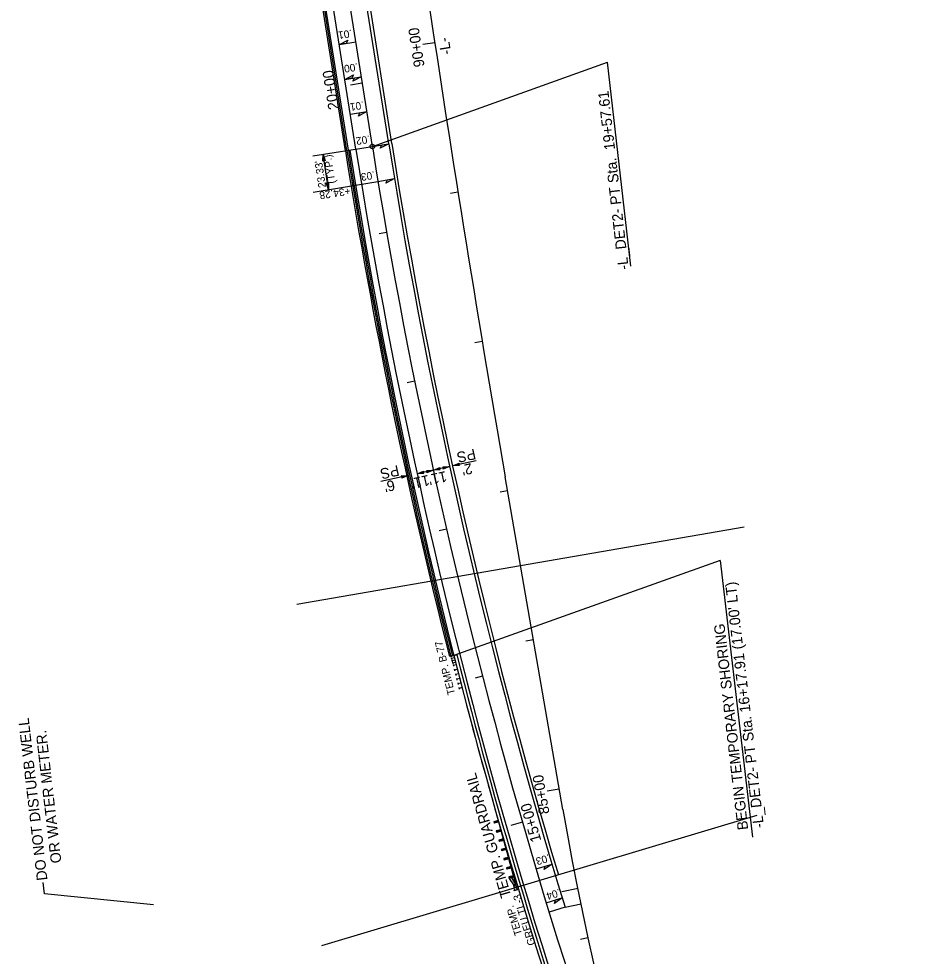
# Model space of a CAD drawing. Extents: x 473658 to 481584, y 489119 to 506230.
# Drawn here: x 478076 to 478674, y 495025 to 495645 of the extents above; entities that cross this region are included whole.
import ezdxf

# ---------------------------------------------------------------- set-up
doc = ezdxf.new("R2010")
doc.units = 0
for name, color, linetype in [('Exist Structure Minor Culvert Topo', 7, 'Continuous'), ('Exist Structure Minor Pipes CMP 60 Inch', 7, 'Continuous'), ('Prop Conc Barrier', 7, 'Continuous'), ('Prop Dimension', 7, 'Continuous'), ('Prop EOT', 7, 'Continuous'), ('Prop Guardrail', 7, 'Continuous'), ('Prop Guardrail Anchor Unit CELL', 7, 'Continuous'), ('Prop Horizontal Alignment', 7, 'Continuous'), ('Prop Horizontal Alignment Direction Label', 7, 'Continuous'), ('Prop Horizontal Alignment Station Label', 7, 'Continuous'), ('Prop Horizontal Alignment Tick Label', 7, 'Continuous'), ('Prop Horizontal Alignment Tick Large', 7, 'Continuous'), ('Prop Horizontal Alignment Tick Small', 7, 'Continuous'), ('Prop Paved Shoulder', 7, 'Continuous'), ('Prop Superelevation  Arrow CELL', 7, 'Continuous'), ('Prop Superelevation Label', 7, 'Continuous'), ('Scratch_Level_3', 7, 'Continuous'), ('Scratch_Level_4', 7, 'Continuous'), ('Scratch_Level_5', 7, 'Continuous'), ('Scratch_Level_6', 7, 'Continuous'), ('Sheet Plan And Profile CELL', 7, 'Continuous'), ('Sheet Profile Grid Major CELL', 7, 'Continuous')]:
    doc.layers.add(name, color=color, linetype=linetype)

msp = doc.modelspace()

# ---------------------------------------------------------------- linework, layer by layer
at = {"layer": 'Exist Structure Minor Culvert Topo'}
for p, q in [((478360.78, 495224.13), (478361.07, 495223.02)), ((478362.86, 495224.07), (478360.93, 495223.57)), ((478361.17, 495222.61), (478361.46, 495221.5)), ((478363.25, 495222.55), (478361.32, 495222.06)), ((478362.86, 495224.07), (478368.55, 495201.91)), ((478361.56, 495221.1), (478361.85, 495219.99)), ((478363.64, 495221.04), (478361.7, 495220.54)), ((478361.95, 495219.58), (478362.24, 495218.48)), ((478364.03, 495219.53), (478362.09, 495219.03)), ((478362.34, 495218.07), (478362.62, 495216.96)), ((478364.42, 495218.01), (478362.48, 495217.52)), ((478363.12, 495215.04), (478363.4, 495213.94)), ((478365.2, 495214.99), (478363.26, 495214.49)), ((478363.89, 495212.02), (478364.18, 495210.91)), ((478365.97, 495211.96), (478364.04, 495211.46)), ((478364.67, 495208.99), (478364.96, 495207.88)), ((478366.75, 495208.93), (478364.81, 495208.44)), ((478365.45, 495205.96), (478365.73, 495204.85)), ((478367.53, 495205.91), (478365.59, 495205.41)), ((478366.22, 495202.94), (478366.51, 495201.83)), ((478368.3, 495202.88), (478366.37, 495202.38))]:
    msp.add_line(p, q, dxfattribs=at)
at = {"layer": 'Exist Structure Minor Pipes CMP 60 Inch'}
msp.add_line((478291.29, 495557.58), (478258.12, 495767.21), dxfattribs=at)
msp.add_arc((481983.35, 496141.85), 3738, 188.99254, 194.22469, dxfattribs=at)
at = {"layer": 'Prop Conc Barrier'}
for p, q in [((478293.31, 495557.93), (478260.02, 495768.31)), ((478306.27, 495497.95), (478306.27, 495497.95))]:
    msp.add_line(p, q, dxfattribs=at)
msp.add_arc((481983.35, 496141.85), 3736, 188.99254, 194.22472, dxfattribs=at)
at = {"layer": 'Prop Dimension'}
for p, q in [((478377.54, 495352.74), (478362.05, 495349.35)), ((478360.1, 495348.92), (478338.61, 495344.22)), ((478332.74, 495342.94), (478314.7, 495338.99)), ((478092.44, 495066.56), (478091.55, 495074.21)), ((478164.55, 495059.32), (478092.44, 495066.56))]:
    msp.add_line(p, q, dxfattribs=at)
for points in [[(478344.79, 495346.37), (478349.35, 495346.57), (478345.1, 495344.82), (478345.49, 495345.73)], [(478353.91, 495346.78), (478349.35, 495346.57), (478353.6, 495348.32), (478353.21, 495347.42)], [(478355.53, 495348.72), (478360.1, 495348.92), (478355.85, 495347.17), (478356.24, 495348.08)], [(478366.61, 495349.56), (478362.05, 495349.35), (478366.3, 495351.1), (478365.91, 495350.19)], [(478328.18, 495342.73), (478332.74, 495342.94), (478328.49, 495341.19), (478328.89, 495342.09)], [(478343.17, 495344.42), (478338.61, 495344.22), (478342.85, 495345.97), (478342.46, 495345.06)]]:
    msp.add_lwpolyline(points, close=True, dxfattribs=at)
at = {"layer": 'Prop EOT'}
for p, q in [((478319.94, 495562.11), (478181.82, 496434.86)), ((478298.21, 495558.67), (478195, 496210.83))]:
    msp.add_line(p, q, dxfattribs=at)
for radius, end in [(3731, 203.7418), (3709, 196.99547)]:
    msp.add_arc((481983.35, 496141.85), radius, 188.99254, end, dxfattribs=at)
at = {"layer": 'Prop Guardrail'}
msp.add_arc((481983.35, 496141.85), 3735, 194.5756, 195.91787, dxfattribs=at)
at = {"layer": 'Prop Guardrail Anchor Unit CELL'}
for p, q in [((478391.56, 495117.49), (478403.8, 495072.37)), ((478392.23, 495115.04), (478389.33, 495114.25)), ((478391.04, 495113.68), (478389.33, 495114.25)), ((478389.33, 495114.25), (478389.59, 495113.29)), ((478389.59, 495113.29), (478390.78, 495114.65)), ((478392.49, 495114.07), (478389.59, 495113.29)), ((478390.78, 495114.65), (478391.04, 495113.68)), ((478390.78, 495114.65), (478392.49, 495114.07)), ((478391.04, 495113.68), (478392.23, 495115.04)), ((478392.49, 495114.07), (478391.04, 495113.68)), ((478392.23, 495115.04), (478392.49, 495114.07)), ((478393.88, 495108.96), (478390.93, 495108.16)), ((478392.67, 495107.59), (478390.93, 495108.16)), ((478390.93, 495108.16), (478391.19, 495107.19)), ((478391.19, 495107.19), (478392.4, 495108.56)), ((478394.14, 495107.99), (478391.19, 495107.19)), ((478392.4, 495108.56), (478392.67, 495107.59)), ((478392.4, 495108.56), (478394.14, 495107.99)), ((478393.88, 495108.96), (478392.67, 495107.59)), ((478395.53, 495102.88), (478392.58, 495102.08)), ((478394.32, 495101.51), (478392.58, 495102.08)), ((478392.58, 495102.08), (478392.85, 495101.11)), ((478392.85, 495101.11), (478394.06, 495102.48)), ((478395.79, 495101.91), (478392.85, 495101.11)), ((478394.06, 495102.48), (478394.32, 495101.51)), ((478394.06, 495102.48), (478395.79, 495101.91)), ((478395.53, 495102.88), (478394.32, 495101.51)), ((478397.18, 495096.79), (478394.25, 495096)), ((478395.97, 495095.43), (478394.25, 495096)), ((478394.25, 495096), (478394.51, 495095.03)), ((478394.51, 495095.03), (478395.71, 495096.4)), ((478397.44, 495095.83), (478394.51, 495095.03)), ((478395.71, 495096.4), (478395.97, 495095.43)), ((478395.71, 495096.4), (478397.44, 495095.83)), ((478397.18, 495096.79), (478395.97, 495095.43)), ((478397.18, 495096.79), (478397.44, 495095.83)), ((478398.82, 495090.71), (478395.8, 495089.89)), ((478397.57, 495089.34), (478395.8, 495089.89)), ((478395.8, 495089.89), (478396.06, 495088.93)), ((478396.06, 495088.93), (478397.31, 495090.3)), ((478399.09, 495089.75), (478396.06, 495088.93)), ((478397.31, 495090.3), (478397.57, 495089.34)), ((478397.31, 495090.3), (478399.09, 495089.75)), ((478398.82, 495090.71), (478397.57, 495089.34)), ((478400.47, 495084.63), (478397.58, 495083.85)), ((478399.29, 495083.27), (478397.58, 495083.85)), ((478397.58, 495083.85), (478397.84, 495082.88)), ((478397.84, 495082.88), (478399.03, 495084.24)), ((478400.74, 495083.67), (478397.84, 495082.88)), ((478399.03, 495084.24), (478399.29, 495083.27)), ((478399.03, 495084.24), (478400.74, 495083.67)), ((478400.47, 495084.63), (478399.29, 495083.27)), ((478402.12, 495078.55), (478399.17, 495077.75)), ((478400.91, 495077.18), (478399.17, 495077.75)), ((478399.17, 495077.75), (478399.43, 495076.78)), ((478399.43, 495076.78), (478400.64, 495078.15)), ((478402.38, 495077.58), (478399.43, 495076.78)), ((478399.43, 495076.78), (478402.22, 495072.46)), ((478400.64, 495078.15), (478400.91, 495077.18)), ((478400.64, 495078.15), (478402.38, 495077.58)), ((478402.12, 495078.55), (478400.91, 495077.18)), ((478400.91, 495077.18), (478403.67, 495072.85)), ((478403.67, 495072.85), (478402.22, 495072.46)), ((478402.22, 495072.46), (478402.35, 495071.98)), ((478403.93, 495071.89), (478402.22, 495072.46)), ((478402.22, 495072.46), (478402.48, 495071.5)), ((478402.48, 495071.5), (478403.67, 495072.85)), ((478403.93, 495071.89), (478402.48, 495071.5)), ((478402.56, 495071.98), (478403.15, 495072.15)), ((478403.13, 495070.01), (478402.56, 495071.98)), ((478402.64, 495068.64), (478403.13, 495070.01)), ((478405.46, 495069.47), (478402.64, 495068.64)), ((478403.15, 495072.15), (478403.73, 495072.32)), ((478403.73, 495072.32), (478404.3, 495070.35)), ((478404.3, 495070.35), (478405.46, 495069.47))]:
    msp.add_line(p, q, dxfattribs=at)
at = {"layer": 'Prop Horizontal Alignment'}
for p, q in [((478309.07, 495560.39), (478170.96, 496433.14)), ((478434.84, 495122.35), (478396.81, 495342.17))]:
    msp.add_line(p, q, dxfattribs=at)
for centre, radius, start, end in [((491911.02, 497680.41), 13715, 187.021509, 189.816184), ((481983.35, 496141.85), 3720, 188.99254, 203.7418), ((480454.83, 495471.85), 2050, 189.81618, 250.32977)]:
    msp.add_arc(centre, radius, start, end, dxfattribs=at)
at = {"layer": 'Prop Horizontal Alignment Station Label'}
for p, q in [((478309.07, 495560.39), (478464.32, 495616.2)), ((478479.87, 495481.31), (478464.32, 495616.2)), ((478538.89, 495286.79), (478362.86, 495224.07)), ((478538.89, 495286.79), (478560.07, 495104.01))]:
    msp.add_line(p, q, dxfattribs=at)
msp.add_circle((478309.07, 495560.39), 1.5, dxfattribs=at)
msp.add_circle((478309.07, 495560.39), 1.5, dxfattribs=at)
at = {"layer": 'Prop Horizontal Alignment Tick Large'}
for p, q in [((478350.31, 495628.98), (478342.4, 495627.79)), ((478302.45, 495602.26), (478294.54, 495601.01)), ((478432.51, 495135.8), (478424.63, 495134.44)), ((478408.18, 495113.94), (478400.5, 495111.73))]:
    msp.add_line(p, q, dxfattribs=at)
at = {"layer": 'Prop Horizontal Alignment Tick Small'}
for p, q in [((478365.62, 495530.17), (478360.69, 495529.38)), ((478318.52, 495503.56), (478313.59, 495502.7)), ((478381.66, 495431.46), (478376.73, 495430.64)), ((478337, 495405.29), (478332.1, 495404.3)), ((478398.42, 495332.87), (478393.49, 495332.02)), ((478358.11, 495307.54), (478353.24, 495306.42)), ((478415.46, 495234.34), (478410.54, 495233.49)), ((478381.85, 495210.4), (478377.01, 495209.15)), ((478451.35, 495037.6), (478446.46, 495036.54))]:
    msp.add_line(p, q, dxfattribs=at)
at = {"layer": 'Prop Paved Shoulder'}
for p, q in [((478321.91, 495562.42), (478183.8, 496435.17)), ((478292.28, 495557.74), (478258.98, 495768.15)), ((478360.93, 495223.57), (478364.8, 495224.55))]:
    msp.add_line(p, q, dxfattribs=at)
for radius, start, end in [(3737, 188.99254, 194.22469), (3707, 188.99254, 196.65704), (3733, 194.22478, 203.7418)]:
    msp.add_arc((481983.35, 496141.85), radius, start, end, dxfattribs=at)
at = {"layer": 'Prop Superelevation  Arrow CELL'}
for points in [[(478287.27, 495627.8), (478292.88, 495630.71), (478291.84, 495628.52)], [(478290.91, 495604.76), (478296.53, 495607.67), (478295.48, 495605.48)], [(478301.78, 495606.48), (478296.16, 495603.56), (478297.21, 495605.75)], [(478305.42, 495583.43), (478299.81, 495580.52), (478300.86, 495582.71)], [(478319.94, 495562.11), (478314.32, 495559.2), (478315.37, 495561.39)], [(478276.4, 495550.67), (478276.49, 495555.23), (478277.96, 495550.88), (478277.08, 495551.33)], [(478323.64, 495539.15), (478318.05, 495536.2), (478319.08, 495538.39)], [(478280.13, 495536.53), (478280.05, 495531.97), (478278.57, 495536.32), (478279.45, 495535.87)], [(478427.74, 495086.23), (478422.56, 495082.6), (478423.31, 495084.91)], [(478434.43, 495063.95), (478429.27, 495060.29), (478430.01, 495062.61)]]:
    msp.add_lwpolyline(points, close=True, dxfattribs=at)
at = {"layer": 'Prop Superelevation Label'}
for p, q in [((478287.27, 495627.8), (478298.13, 495629.52)), ((478290.91, 495604.76), (478301.78, 495606.48)), ((478294.56, 495581.71), (478305.42, 495583.43)), ((478269.82, 495554.18), (478309.07, 495560.39)), ((478309.07, 495560.39), (478319.94, 495562.11)), ((478312.79, 495537.36), (478323.64, 495539.15)), ((478270.04, 495530.32), (478312.79, 495537.36)), ((478417.2, 495083.1), (478427.74, 495086.23)), ((478423.91, 495060.75), (478434.43, 495063.95))]:
    msp.add_line(p, q, dxfattribs=at)
msp.add_arc((479293.49, 495698.8), 1027.09, 188.03508, 189.34818, dxfattribs=at)
at = {"layer": 'Scratch_Level_3'}
msp.add_line((478434.22, 495068.11), (478444.96, 495070.3), dxfattribs=at)
at = {"layer": 'Scratch_Level_4'}
msp.add_arc((481983.35, 496141.85), 3735, 188.99254, 203.7418, dxfattribs=at)
at = {"layer": 'Scratch_Level_5'}
msp.add_line((478275.74, 495032.55), (478563.15, 495118.54), dxfattribs=at)
at = {"layer": 'Scratch_Level_6'}
for q in [(478425.81, 495054.51), (478447.08, 495059.95)]:
    msp.add_line((478436.33, 495057.72), q, dxfattribs=at)
at = {"layer": 'Sheet Plan And Profile CELL'}
msp.add_line((478259.14, 495258.03), (478554.74, 495309.18), dxfattribs=at)

# ---------------------------------------------------------------- texts
at = {"layer": 'Prop Dimension'}
for s, rotation, p in [('PS', 192.34425, (478376.51, 495360.81)), ('PS', 192.34425, (478325.93, 495349.94)), ("2'", 192.34425, (478374.32, 495351.24)), ("6'", 192.34425, (478323.09, 495340.23)), ("11'", 192.34425, (478346.05, 495343.51)), ("11'", 192.34425, (478357.5, 495346.02)), ('DO NOT DISTURB WELL ', 96.60736, (478094.52, 495075.78)), ('OR WATER METER.', 96.60736, (478103.76, 495087.25))]:
    msp.add_text(s, height=7, rotation=rotation, dxfattribs=at).set_placement(p)
at = {"layer": 'Prop Guardrail Anchor Unit CELL'}
for s, rotation, p in [('TEMP. B-77', 103.82223, (478363.8, 495198.74)), ('GREU TL-3', 106.99522, (478416.89, 495033.37)), ('TEMP. ', 106.99522, (478408.04, 495039.89))]:
    msp.add_text(s, height=5, rotation=rotation, dxfattribs=at).set_placement(p)
at = {"layer": 'Prop Horizontal Alignment Direction Label'}
msp.add_text('-L-', height=7, rotation=98.99254, dxfattribs=at).set_placement((478361.26, 495621.57))
at = {"layer": 'Prop Horizontal Alignment Station Label'}
for s, rotation, p in [('-L_DET2- PT Sta.  19+57.61', 96.51408, (478478.45, 495479.34)), ("-L_DET2- PT Sta. 16+17.91 (17.00' LT)", 96.60736, (478567.79, 495110.38)), ('BEGIN TEMPORARY SHORING', 96.60736, (478557.36, 495109.17))]:
    msp.add_text(s, height=7, rotation=rotation, dxfattribs=at).set_placement(p)
at = {"layer": 'Prop Horizontal Alignment Tick Label'}
for s, rotation, p in [('90+00', 98.60232, (478343.57, 495613.36)), ('20+00', 98.99254, (478287.08, 495585.25)), ('85+00', 99.81618, (478426.14, 495119.82)), ('15+00', 106.04075, (478420.74, 495101.86))]:
    msp.add_text(s, height=7, rotation=rotation, dxfattribs=at).set_placement(p)
at = {"layer": 'Prop Superelevation Label'}
for s, rotation, p in [('.01', 188.9925, (478295.32, 495637.64)), ('.00', 188.9925, (478299.23, 495615.49)), ('.01', 188.9925, (478303.08, 495590.25)), ('.02', 188.9925, (478307.11, 495567.73)), ('(TYP.)', 98.66108, (478284.71, 495536.22)), ("23.33'", 98.66108, (478278.5, 495533.48)), ('.03', 189.35193, (478310.34, 495544.04)), ('+34.28', 188.66108, (478294.21, 495533.46)), ('.03', 196.53562, (478425.54, 495092.86)), ('.04', 196.89495, (478432.39, 495069.98))]:
    msp.add_text(s, height=5, rotation=rotation, dxfattribs=at).set_placement(p)
at = {"layer": 'Sheet Profile Grid Major CELL'}
for s, p in [('GUARDRAIL', (478392.4, 495094.64)), ('TEMP. ', (478400.9, 495065.09))]:
    msp.add_text(s, height=7, rotation=106.04965, dxfattribs=at).set_placement(p)

doc.saveas('drawing.dxf')
